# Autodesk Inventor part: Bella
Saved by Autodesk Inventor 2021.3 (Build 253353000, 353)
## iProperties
Created: 2022-09
Part Number: Bella
Material: Generic
Document SubType Name: Modeling
Designer: Administrator
Density: 1 g/cm^3
Appearance: Default
Title: Bella v3
Author: Administrator
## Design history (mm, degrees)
feature "Bella" [Body]
feature "Socket Body" [Body]
feature "Shade Ring" [Body]
feature "Shade Ring +Collar" [Body]
feature "Socket" [Body]
feature "Body1"
feature "Metal Strain Relief" [Body]
feature "Fabric Cord (1)" [Body]
feature "Stem (Threaded)" [Body]
feature "Cap (Threaded)" [Body]
feature "T8-Bulb" [Body]
body "Solid1"
body "Solid2"
body "Solid3"
body "Solid4"
body "Solid5"
body "Solid6"
body "Solid7"
body "Solid8"
body "Solid9"
body "Solid10"
body "Solid11"
